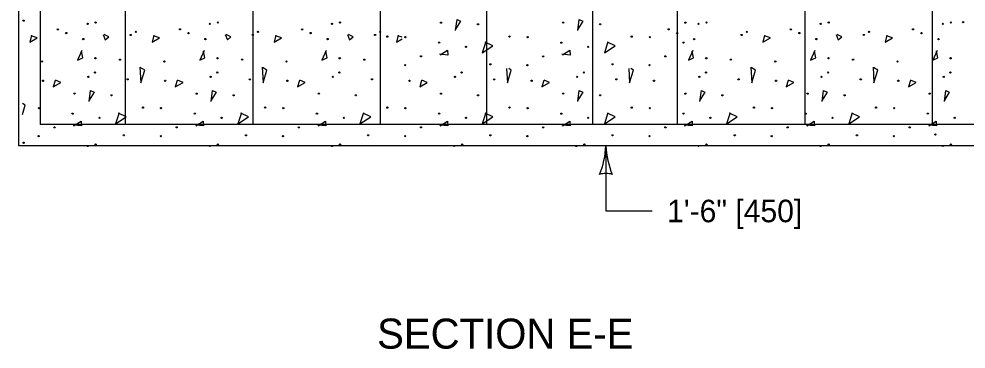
# Model space of a CAD drawing. Extents: x 49991.4 to 50021, y 49987.6 to 50011.4.
# Drawn here: x 50012.344 to 50014.87, y 49996.614 to 49997.494 of the extents above; entities that cross this region are included whole.
import ezdxf

# ---------------------------------------------------------------- set-up
doc = ezdxf.new("R2010")
doc.units = 0
for name, color, linetype in [('Level 1', 7, 'Continuous'), ('Level 2', 7, 'Continuous'), ('Level 3', 7, 'Continuous')]:
    doc.layers.add(name, color=color, linetype=linetype)

msp = doc.modelspace()

# ---------------------------------------------------------------- linework, layer by layer
at = {"layer": 'Level 1'}
for p, q in [((50012.3438, 49997.1556), (50012.3438, 49998.3456)), ((50012.4004, 49998.289), (50012.4004, 49997.2122)), ((50012.6271, 49998.289), (50012.6271, 49997.2122)), ((50012.9671, 49998.289), (50012.9671, 49997.2122)), ((50013.3071, 49998.289), (50013.3071, 49997.2122)), ((50014.1004, 49997.2122), (50014.1004, 49998.289)), ((50014.4404, 49997.2122), (50014.4404, 49998.289)), ((50014.7804, 49997.2122), (50014.7804, 49998.289)), ((50013.5904, 49997.609), (50013.5904, 49997.2122)), ((50013.8737, 49997.609), (50013.8737, 49997.2122)), ((50015.007, 49997.2122), (50012.4004, 49997.2122)), ((50015.0637, 49997.1556), (50012.3438, 49997.1556))]:
    msp.add_line(p, q, dxfattribs=at)
for points in [[(50013.5084, 49997.4628), (50013.5121, 49997.4919), (50013.5215, 49997.4876), (50013.5084, 49997.4664)], [(50013.8343, 49997.4628), (50013.8379, 49997.4919), (50013.8474, 49997.4876), (50013.8343, 49997.4664)], [(50012.3773, 49997.4504), (50012.373, 49997.4322), (50012.3926, 49997.4439), (50012.3766, 49997.449)], [(50012.568, 49997.4526), (50012.5739, 49997.438), (50012.5834, 49997.446), (50012.571, 49997.4526)], [(50012.7031, 49997.4504), (50012.6988, 49997.4322), (50012.7185, 49997.4439), (50012.7024, 49997.449)], [(50012.894, 49997.4526), (50012.8997, 49997.438), (50012.9093, 49997.446), (50012.8968, 49997.4526)], [(50013.029, 49997.4504), (50013.0246, 49997.4322), (50013.0443, 49997.4439), (50013.0282, 49997.449)], [(50013.2198, 49997.4526), (50013.2256, 49997.438), (50013.2351, 49997.446), (50013.2227, 49997.4526)], [(50013.3549, 49997.4504), (50013.3504, 49997.4322)], [(50013.3504, 49997.4322), (50013.3657, 49997.4412)], [(50013.3657, 49997.4452), (50013.3541, 49997.449)], [(50014.3324, 49997.4504), (50014.328, 49997.4322), (50014.3477, 49997.4439), (50014.3317, 49997.449)], [(50014.5232, 49997.4526), (50014.529, 49997.438), (50014.5385, 49997.446), (50014.5261, 49997.4526)], [(50014.6583, 49997.4504), (50014.6539, 49997.4322), (50014.6736, 49997.4439), (50014.6575, 49997.449)], [(50013.5887, 49997.4328), (50013.5793, 49997.4036), (50013.6077, 49997.4219), (50013.5872, 49997.4321)], [(50013.9146, 49997.4328), (50013.9051, 49997.4036), (50013.9335, 49997.4219), (50013.9131, 49997.4321)], [(50012.5117, 49997.4095), (50012.5, 49997.3839), (50012.5138, 49997.3905), (50012.5102, 49997.4081)], [(50012.8375, 49997.4095), (50012.8258, 49997.3839), (50012.8397, 49997.3905), (50012.836, 49997.4081)], [(50013.1633, 49997.4095), (50013.1517, 49997.3839), (50013.1656, 49997.3905), (50013.1619, 49997.4081)], [(50013.4673, 49997.3985), (50013.487, 49997.4102), (50013.4878, 49997.3977), (50013.4658, 49997.3999)], [(50013.7931, 49997.3985), (50013.8128, 49997.4102), (50013.8136, 49997.3977), (50013.7918, 49997.3999)], [(50014.1409, 49997.4095), (50014.1292, 49997.3839), (50014.1431, 49997.3905), (50014.1394, 49997.4081)], [(50014.4667, 49997.4095), (50014.4551, 49997.3839), (50014.469, 49997.3905), (50014.4653, 49997.4081)], [(50014.7927, 49997.4095), (50014.7809, 49997.3839), (50014.7948, 49997.3905), (50014.7912, 49997.4081)], [(50012.6666, 49997.3657), (50012.6689, 49997.3233), (50012.6791, 49997.3576), (50012.6674, 49997.3642)], [(50012.9924, 49997.3657), (50012.9947, 49997.3233), (50013.0049, 49997.3576), (50012.9932, 49997.3642)], [(50014.2958, 49997.3657), (50014.2981, 49997.3233), (50014.3083, 49997.3576), (50014.2966, 49997.3642)], [(50014.6218, 49997.3657), (50014.6239, 49997.3233), (50014.6341, 49997.3576), (50014.6225, 49997.3642)], [(50013.6444, 49997.3614), (50013.6463, 49997.3233)], [(50013.6463, 49997.3233), (50013.6567, 49997.3576)], [(50013.6567, 49997.3576), (50013.6501, 49997.3614)], [(50013.9702, 49997.3614), (50013.9723, 49997.3233)], [(50013.9723, 49997.3233), (50013.9825, 49997.3576)], [(50013.9825, 49997.3576), (50013.9759, 49997.3614)], [(50012.4401, 49997.3299), (50012.435, 49997.3131), (50012.4555, 49997.3241), (50012.4409, 49997.3307)], [(50012.766, 49997.3299), (50012.7608, 49997.3131), (50012.7813, 49997.3241), (50012.7667, 49997.3307)], [(50013.0918, 49997.3299), (50013.0867, 49997.3131), (50013.1071, 49997.3241), (50013.0925, 49997.3307)], [(50013.4176, 49997.3299), (50013.4125, 49997.3131), (50013.4329, 49997.3241), (50013.4184, 49997.3307)], [(50013.7435, 49997.3299), (50013.7384, 49997.3131), (50013.7589, 49997.3241), (50013.7443, 49997.3307)], [(50014.3952, 49997.3299), (50014.3901, 49997.3131), (50014.4105, 49997.3241), (50014.3959, 49997.3307)], [(50014.7211, 49997.3299), (50014.716, 49997.3131), (50014.7364, 49997.3241), (50014.7219, 49997.3307)], [(50012.5308, 49997.2737), (50012.5345, 49997.3029), (50012.544, 49997.2985), (50012.5308, 49997.2774)], [(50012.8567, 49997.2737), (50012.8603, 49997.3029), (50012.8698, 49997.2985), (50012.8567, 49997.2774)], [(50013.8343, 49997.2737), (50013.8379, 49997.3029), (50013.8474, 49997.2985), (50013.8343, 49997.2774)], [(50014.1601, 49997.2737), (50014.1637, 49997.3029), (50014.1732, 49997.2985), (50014.1601, 49997.2774)], [(50014.4859, 49997.2737), (50014.4895, 49997.3029), (50014.499, 49997.2985), (50014.4859, 49997.2774)], [(50014.8118, 49997.2737), (50014.8155, 49997.3029), (50014.8249, 49997.2985), (50014.8118, 49997.2774)], [(50012.3606, 49997.2641), (50012.3531, 49997.2683)], [(50012.3531, 49997.239), (50012.3606, 49997.2641)], [(50012.6112, 49997.2437), (50012.6017, 49997.2145), (50012.6301, 49997.2327), (50012.6097, 49997.2431)], [(50012.937, 49997.2437), (50012.9275, 49997.2145), (50012.9559, 49997.2327), (50012.9355, 49997.2431)], [(50013.2628, 49997.2437), (50013.2533, 49997.2145), (50013.2819, 49997.2327), (50013.2614, 49997.2431)], [(50013.5887, 49997.2437), (50013.5793, 49997.2145), (50013.6077, 49997.2327), (50013.5872, 49997.2431)], [(50013.9146, 49997.2437), (50013.9051, 49997.2145), (50013.9335, 49997.2327), (50013.9131, 49997.2431)], [(50014.2404, 49997.2437), (50014.2309, 49997.2145), (50014.2594, 49997.2327), (50014.239, 49997.2431)], [(50014.5662, 49997.2437), (50014.5567, 49997.2145), (50014.5853, 49997.2327), (50014.5648, 49997.2431)], [(50012.4897, 49997.2094), (50012.5094, 49997.2211), (50012.5102, 49997.2087), (50012.4883, 49997.2109)], [(50012.8156, 49997.2094), (50012.8354, 49997.2211), (50012.836, 49997.2087), (50012.8142, 49997.2109)], [(50013.1415, 49997.2094), (50013.1612, 49997.2211), (50013.1619, 49997.2087), (50013.14, 49997.2109)], [(50013.4673, 49997.2094), (50013.487, 49997.2211), (50013.4878, 49997.2087), (50013.4658, 49997.2109)], [(50013.7931, 49997.2094), (50013.8128, 49997.2211), (50013.8136, 49997.2087), (50013.7918, 49997.2109)], [(50014.119, 49997.2094), (50014.1388, 49997.2211), (50014.1394, 49997.2087), (50014.1176, 49997.2109)], [(50014.4449, 49997.2094), (50014.4646, 49997.2211), (50014.4653, 49997.2087), (50014.4434, 49997.2109)], [(50014.7707, 49997.2094), (50014.7904, 49997.2211), (50014.7912, 49997.2087), (50014.7692, 49997.2109)]]:
    msp.add_lwpolyline(points, dxfattribs=at)
for centre in [(50012.3561, 49997.4893), (50012.4474, 49997.466), (50012.5269, 49997.4807), (50012.5483, 49997.4843), (50012.7732, 49997.466), (50012.8528, 49997.4807), (50012.8741, 49997.4843), (50013.0991, 49997.466), (50013.1787, 49997.4807), (50013.2, 49997.4843), (50013.4695, 49997.4839), (50013.5682, 49997.4795), (50013.7953, 49997.4839), (50013.894, 49997.4795), (50014.0766, 49997.466), (50014.1212, 49997.4839), (50014.1562, 49997.4807), (50014.1775, 49997.4843), (50014.4025, 49997.466), (50014.4821, 49997.4807), (50014.5034, 49997.4843), (50014.7283, 49997.466), (50014.8079, 49997.4807), (50014.8292, 49997.4843), (50014.862, 49997.4855), (50012.47, 49997.4562), (50012.5153, 49997.4401), (50012.6418, 49997.4511), (50012.6556, 49997.4595), (50012.7959, 49997.4562), (50012.8411, 49997.4401), (50012.9676, 49997.4511), (50012.9815, 49997.4595), (50013.1217, 49997.4562), (50013.167, 49997.4401), (50013.2935, 49997.4511), (50013.3073, 49997.4595), (50013.3263, 49997.4467), (50013.3745, 49997.4452), (50013.6522, 49997.4467), (50013.7004, 49997.4452), (50013.978, 49997.4467), (50014.0262, 49997.4452), (50014.0993, 49997.4562), (50014.1445, 49997.4401), (50014.271, 49997.4511), (50014.2849, 49997.4595), (50014.4251, 49997.4562), (50014.4704, 49997.4401), (50014.5969, 49997.4511), (50014.6107, 49997.4595), (50014.751, 49997.4562), (50014.7962, 49997.4401), (50013.4644, 49997.4306), (50013.5361, 49997.4196), (50013.7902, 49997.4306), (50013.8619, 49997.4196), (50014.1161, 49997.4306), (50012.5476, 49997.389), (50012.8734, 49997.389), (50013.1993, 49997.389), (50013.4161, 49997.3941), (50013.742, 49997.3941), (50014.0678, 49997.3941), (50014.1768, 49997.389), (50014.5027, 49997.389), (50014.8285, 49997.389), (50012.4057, 49997.3803), (50012.6133, 49997.3854), (50012.7316, 49997.3803), (50012.9391, 49997.3854), (50013.0574, 49997.3803), (50013.265, 49997.3854), (50013.3738, 49997.3707), (50013.6011, 49997.3729), (50013.6997, 49997.3707), (50013.9269, 49997.3729), (50014.0255, 49997.3707), (50014.2425, 49997.3854), (50014.3608, 49997.3803), (50014.5684, 49997.3854), (50014.6867, 49997.3803), (50012.5291, 49997.3394), (50012.5468, 49997.351), (50012.855, 49997.3394), (50012.8727, 49997.351), (50013.1808, 49997.3394), (50013.1985, 49997.351), (50013.5067, 49997.3394), (50013.5244, 49997.351), (50013.8325, 49997.3394), (50013.8502, 49997.351), (50014.1584, 49997.3394), (50014.1761, 49997.351), (50014.4842, 49997.3394), (50014.502, 49997.351), (50014.8101, 49997.3394), (50014.8278, 49997.351), (50012.4079, 49997.3291), (50012.6337, 49997.3328), (50012.7338, 49997.3291), (50012.9596, 49997.3328), (50013.0596, 49997.3291), (50013.2854, 49997.3328), (50013.3855, 49997.3291), (50013.6113, 49997.3328), (50013.7113, 49997.3291), (50013.9371, 49997.3328), (50014.0372, 49997.3291), (50014.263, 49997.3328), (50014.363, 49997.3291), (50014.5888, 49997.3328), (50014.6889, 49997.3291), (50012.4919, 49997.2948), (50012.5906, 49997.2904), (50012.8178, 49997.2948), (50012.9165, 49997.2904), (50013.1436, 49997.2948), (50013.2423, 49997.2904), (50013.4695, 49997.2948), (50013.5682, 49997.2904), (50013.7953, 49997.2948), (50013.894, 49997.2904), (50014.1212, 49997.2948), (50014.2199, 49997.2904), (50014.447, 49997.2948), (50014.5458, 49997.2904), (50014.7729, 49997.2948), (50012.397, 49997.2561), (50012.4868, 49997.2415), (50012.6746, 49997.2576), (50012.7228, 49997.2561), (50012.8127, 49997.2415), (50013.0005, 49997.2576), (50013.0487, 49997.2561), (50013.1385, 49997.2415), (50013.3263, 49997.2576), (50013.3745, 49997.2561), (50013.4644, 49997.2415), (50013.6522, 49997.2576), (50013.7004, 49997.2561), (50013.7902, 49997.2415), (50013.978, 49997.2576), (50014.0262, 49997.2561), (50014.1161, 49997.2415), (50014.3039, 49997.2576), (50014.3521, 49997.2561), (50014.4419, 49997.2415), (50014.6297, 49997.2576), (50014.6779, 49997.2561), (50014.7678, 49997.2415), (50012.5585, 49997.2305), (50012.8844, 49997.2305), (50013.2102, 49997.2305), (50013.5361, 49997.2305), (50013.8619, 49997.2305), (50014.1878, 49997.2305), (50014.5136, 49997.2305), (50014.8395, 49997.2305), (50012.4386, 49997.205), (50012.7644, 49997.205), (50013.0903, 49997.205), (50013.4161, 49997.205), (50013.742, 49997.205), (50014.0678, 49997.205), (50014.3937, 49997.205), (50014.7195, 49997.205), (50014.7879, 49997.1861), (50012.3561, 49997.164), (50012.3963, 49997.1816), (50012.6235, 49997.1838), (50012.7221, 49997.1816), (50012.9494, 49997.1838), (50013.048, 49997.1816), (50013.2752, 49997.1838), (50013.3738, 49997.1816), (50013.6011, 49997.1838), (50013.6997, 49997.1816), (50013.9269, 49997.1838), (50014.0255, 49997.1816), (50014.2528, 49997.1838), (50014.3514, 49997.1816), (50014.5786, 49997.1838), (50014.6772, 49997.1816), (50012.5269, 49997.1553), (50012.5483, 49997.159), (50012.8528, 49997.1553), (50012.8741, 49997.159), (50013.1787, 49997.1553), (50013.2, 49997.159), (50013.5045, 49997.1553), (50013.5258, 49997.159), (50013.8304, 49997.1553), (50013.8517, 49997.159), (50014.1562, 49997.1553), (50014.1775, 49997.159), (50014.4821, 49997.1553), (50014.5034, 49997.159), (50014.8079, 49997.1553), (50014.8292, 49997.159)]:
    msp.add_circle(centre, 0.00165, dxfattribs=at)
at = {"layer": 'Level 3'}
for p, q in [((50013.9092, 49997.1556), (50013.9092, 49996.9822)), ((50013.9092, 49996.9822), (50014.0324, 49996.9822))]:
    msp.add_line(p, q, dxfattribs=at)
for centre, radius, start, end in [((50013.687, 49997.1647), 0.2223, 337.456, 357.6395), ((50014.1419, 49997.1671), 0.233, 182.8273, 202.0772), ((50013.9092, 49997.0274), 0.0548, 72.1388, 107.8612)]:
    msp.add_arc(centre, radius, start, end, dxfattribs=at)

# ---------------------------------------------------------------- texts
at = {"layer": 'Level 2'}
for s, height, p in [('1\'-6" [450]', 0.06, (50014.0724, 49996.9522)), ('SECTION E-E', 0.08, (50013.299, 49996.6155))]:
    msp.add_text(s, height=height, dxfattribs=at).set_placement(p)

doc.saveas('drawing.dxf')
